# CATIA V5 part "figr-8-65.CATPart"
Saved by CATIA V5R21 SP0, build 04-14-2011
Part number: Part1
Bounding box of the stored display mesh (mm): x -53.439 to 53.439, y -63.41 to 103.633, z -17.5 to 34.5
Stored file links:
  D:\CATIA V5R21 E-RESOURCES\CATIA-V5R21\catia-v5r21-prt\c08-catia-v5r20-prt\c08-catia-v5r21-figr-8-65.CATPart
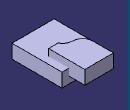
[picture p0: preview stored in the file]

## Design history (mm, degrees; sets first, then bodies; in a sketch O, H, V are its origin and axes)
Body1 (main body)
  Sketch1 on xy-plane, origin (0, 0, 0), H (1, 0, 0), V (0, 1, 0)
    line L1 (-53.4395, 63.4095) -> (53.4395, 63.4095)
    line L2 (53.4395, 63.4095) -> (53.4395, -63.4095)
    line L3 (53.4395, -63.4095) -> (-53.4395, -63.4095)
    line L4 (-53.4395, -63.4095) -> (-53.4395, 63.4095)
    axis line L5 (53.4395, -63.4095) -> (-53.4395, 63.4095)
    horizontal: L1 H, L3 H
    vertical: L2 V, L4 V
    midpoint: O L5
  Pad1: profile Sketch1, direction (0, 0, 1), length 17.5, mirrored extent
Body2
  Sketch2 on xy-plane, origin (0, 0, 0), H (1, 0, 0), V (0, 1, 0)
    line L1 (-36.9238, 103.6333) -> (-36.9238, 51.4035)
    arc A1 centre (-11.4307, 51.4035) radius 25.4931 from (-36.9238, 51.4035) to (-11.4307, 25.9104) ccw
    arc A2 centre (-11.4307, 0.4172) radius 25.4931 from (-11.4307, 25.9104) to (11.4981, 11.5602) cw
    line L2 (11.4981, 11.5602) -> (35.6176, 11.5602)
    line L3 (35.6176, 11.5602) -> (35.6176, 103.6333)
    line L4 (35.6176, 103.6333) -> (-36.9238, 103.6333)
    vertical: L1 V, L3 V
    tangency: A1 L1, A2 L1, A2 A1
    horizontal: L2 H, L4 H
  Pad2: profile Sketch2, direction (0, 0, 1), length 34.5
